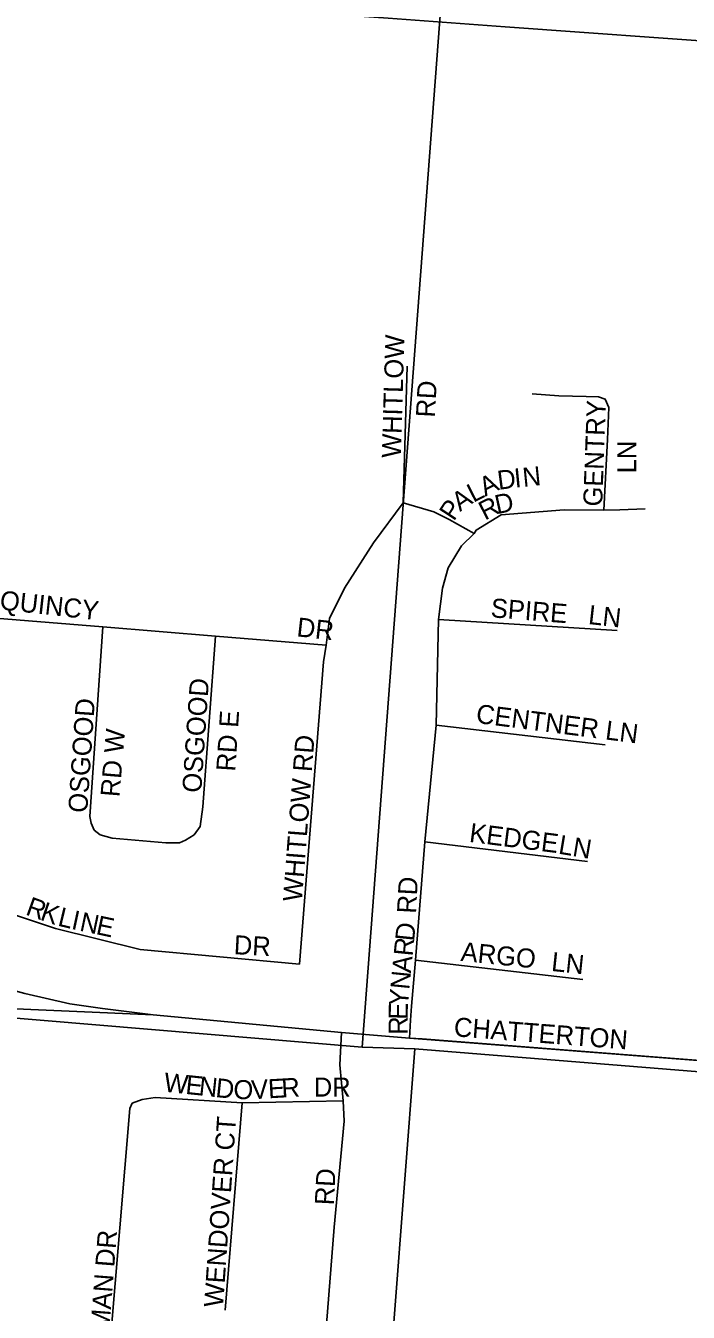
# Model space of a CAD drawing. Extents: x 0 to 34, y 0 to 22.
# Drawn here: x 8.094 to 8.423, y 17.781 to 18.421 of the extents above; entities that cross this region are included whole.
import ezdxf

# ---------------------------------------------------------------- set-up
doc = ezdxf.new("R2010")
doc.units = 0
for name, color, linetype in [('GM_X_City_Street', 7, 'Continuous'), ('GM_X_City_Street_Text', 7, 'Continuous'), ('GM_X_County_Road', 7, 'Continuous'), ('GM_X_Section', 7, 'Continuous'), ('GM_X_Township', 7, 'Continuous'), ('GM_X_Township_Subdivision', 7, 'Continuous'), ('GM_X_Township_Subdivision_Text', 7, 'Continuous')]:
    doc.layers.add(name, color=color, linetype=linetype)

msp = doc.modelspace()

# ---------------------------------------------------------------- linework, layer by layer
at = {"layer": 'GM_X_City_Street'}
for points in [[(7.61286, 18.47677), (7.73377, 18.46739), (7.82057, 18.46016), (7.91346, 18.4521), (8.05978, 18.44059), (8.20725, 18.42941), (8.274, 18.42481), (8.3322, 18.42053), (8.44761, 18.41231)], [(8.28157, 18.18394), (8.28355, 18.25186)], [(8.38117, 18.18027), (8.383, 18.2153), (8.3837, 18.23122), (8.38189, 18.23543), (8.37851, 18.23664), (8.37247, 18.23676), (8.35886, 18.23704), (8.34565, 18.23806)], [(8.28157, 18.18394), (8.29684, 18.17948), (8.30432, 18.17553), (8.31679, 18.16867)], [(8.31679, 18.16867), (8.31783, 18.17032), (8.33016, 18.17796), (8.36147, 18.18046), (8.38117, 18.18027), (8.38918, 18.18046), (8.4017, 18.18094)], [(8.28461, 17.91779), (8.2851, 17.92667), (8.2856, 17.9336), (8.28772, 17.95646), (8.29237, 18.01529), (8.29788, 18.07327), (8.29913, 18.12584), (8.30099, 18.14145), (8.30383, 18.15163), (8.31049, 18.16244), (8.31679, 18.16867)], [(8.29913, 18.12584), (8.38789, 18.12032)], [(8.29788, 18.07327), (8.38184, 18.06352)], [(8.29237, 18.01529), (8.37311, 18.00563)], [(8.28772, 17.95646), (8.3708, 17.94686)], [(8.2909, 17.9173), (8.63956, 17.89017), (9.29091, 17.83807)]]:
    msp.add_lwpolyline(points, dxfattribs=at)
at = {"layer": 'GM_X_County_Road'}
for points in [[(7.6551, 18.02038), (7.67615, 18.02597), (7.69834, 18.03139), (7.71725, 18.03583), (7.72744, 18.03764), (7.73747, 18.03847), (7.75375, 18.0383), (7.77627, 18.03682), (7.81129, 18.03271), (7.84861, 18.0258), (7.86752, 18.02153), (7.88712, 18.01651), (7.92611, 18.0042), (7.95605, 17.99275), (7.98227, 17.98158), (8.00743, 17.96991), (8.01844, 17.96498), (8.02732, 17.96136), (8.04475, 17.95429), (8.06973, 17.9464), (8.09357, 17.93998), (8.11592, 17.93484), (8.1322, 17.93242), (8.1521, 17.92995)], [(8.1521, 17.92995), (8.15736, 17.9293), (8.2509, 17.92059), (8.28461, 17.91779), (8.2909, 17.9173)]]:
    msp.add_lwpolyline(points, dxfattribs=at)
at = {"layer": 'GM_X_Section'}
for points in [[(7.83199, 18.97493), (8.33817, 18.93281), (8.26119, 17.91328), (7.7594, 17.95531)], [(8.33817, 18.93281), (8.85845, 18.89016), (8.78533, 17.87214), (8.28732, 17.91243), (8.26119, 17.91328)], [(7.25608, 17.99704), (7.7594, 17.95531), (8.26119, 17.91328), (8.28732, 17.91243), (8.21553, 16.97509), (7.19182, 17.04453)], [(8.28732, 17.91243), (8.78533, 17.87214), (9.29851, 17.83319), (9.21917, 16.9042), (8.21553, 16.97509)]]:
    msp.add_lwpolyline(points, close=True, dxfattribs=at)
at = {"layer": 'GM_X_Township'}
for points in [[(5.51769, 18.13119), (5.87625, 18.1039), (6.03605, 18.09206), (6.63383, 18.04603), (6.72474, 18.03863), (6.7448, 18.03814), (6.76124, 18.03764), (6.90082, 18.02498), (7.39535, 17.98733), (7.4612, 17.98313), (7.48383, 17.98347), (7.50256, 17.98423), (7.57966, 17.97294), (7.66873, 17.96768), (7.96341, 17.93943), (7.99401, 17.9365), (8.15736, 17.9293), (8.25091, 17.92059), (8.28461, 17.91779), (8.63956, 17.89017), (9.29091, 17.83808), (9.37362, 17.83148), (9.4, 17.82945)], [(9.4, 17.82945), (9.37362, 17.83148), (9.29091, 17.83808), (8.63956, 17.89017), (8.28461, 17.91779), (8.25091, 17.92059), (8.15736, 17.9293), (7.99401, 17.9365), (7.96341, 17.93943), (7.66873, 17.96768), (7.57966, 17.97294), (7.50256, 17.98423), (7.48383, 17.98347), (7.4612, 17.98313), (7.39535, 17.98733), (6.90082, 18.02498), (6.76124, 18.03764), (6.7448, 18.03814), (6.72474, 18.03863), (6.63383, 18.04603), (6.03605, 18.09206), (5.87625, 18.1039), (5.51769, 18.13119)]]:
    msp.add_lwpolyline(points, dxfattribs=at)
at = {"layer": 'GM_X_Township_Subdivision'}
for points in [[(8.23009, 17.95456), (8.24199, 18.10479), (8.2432, 18.11304), (8.24499, 18.1264), (8.25244, 18.14148), (8.26684, 18.16404), (8.28157, 18.18394)], [(8.07888, 18.12659), (8.13236, 18.12218), (8.18831, 18.11757), (8.2432, 18.11304)], [(8.12802, 18.02112), (8.12656, 18.02457), (8.12585, 18.028), (8.13236, 18.12218)], [(8.17766, 18.01882), (8.18076, 18.02295), (8.18206, 18.03281), (8.18831, 18.11757)], [(7.91845, 18.0533), (7.92969, 18.04438), (7.94171, 18.03735), (7.9589, 18.02921), (7.97408, 18.02203), (8.00216, 18.01282), (8.01153, 18.00854), (8.05954, 17.98931), (8.06875, 17.98553), (8.10886, 17.97221), (8.15095, 17.96188), (8.23009, 17.95456)], [(8.12802, 18.02112), (8.13101, 18.01879), (8.13706, 18.01718), (8.16356, 18.01486), (8.17039, 18.01475), (8.17344, 18.01623), (8.17766, 18.01882)], [(8.22144, 17.49905), (8.23877, 17.71644), (8.24732, 17.8237), (8.25217, 17.87646), (8.25174, 17.88662), (8.25005, 17.90439), (8.2509, 17.92059)], [(8.13644, 17.72798), (8.13423, 17.73181), (8.13355, 17.73638), (8.14576, 17.88279), (8.14694, 17.88543)], [(8.14694, 17.88543), (8.1519, 17.88725), (8.15836, 17.88829), (8.20157, 17.88552), (8.25174, 17.88662)], [(8.19304, 17.78253), (8.20157, 17.88552)]]:
    msp.add_lwpolyline(points, dxfattribs=at)

# ---------------------------------------------------------------- texts
at = {"layer": 'GM_X_City_Street_Text'}
for s, rotation, p in [('WHITLOW', 88.31625, (8.28037, 18.20612)), ('RD', 86.98901, (8.29729, 18.22615)), ('GENTRY', 87.9557, (8.38037, 18.18196)), ('LN', 90, (8.39731, 18.19857)), ('D', 7.47476, (8.32893, 18.19032)), ('I', 5.69319, (8.33711, 18.19139)), ('N', 5.68677, (8.34125, 18.19181)), ('L', 26.78499, (8.31634, 18.18381)), ('A', 26.75076, (8.32229, 18.18681)), ('A', 34.29016, (8.30973, 18.17928)), ('R', 27.37963, (8.32217, 18.17495)), ('D', 12.29171, (8.32821, 18.17818)), ('P', 56.57518, (8.30674, 18.17441)), ('SPIRE', 355.48827, (8.32479, 18.12701)), ('LN', 353.65181, (8.37317, 18.12367)), ('CENTNER LN', 352.71239, (8.31737, 18.0745)), ('KEDGE', 352.72451, (8.31404, 18.01533)), ('LN', 350.5298, (8.35827, 18.00949)), ('RD', 86.98901, (8.2879, 17.97949)), ('D', 84.28505, (8.28693, 17.96567)), ('R', 84.28457, (8.28619, 17.95821)), ('ARGO', 354.14185, (8.30983, 17.95617)), ('A', 84.28505, (8.28536, 17.94991)), ('LN', 353.99459, (8.35483, 17.95117)), ('N', 84.28505, (8.28453, 17.94162)), ('Y', 85.36159, (8.28386, 17.93336)), ('E', 88.98915, (8.28375, 17.92686)), ('R', 89.87855, (8.28373, 17.9194)), ('CHATTERTON', 355.6489, (8.30645, 17.91868))]:
    msp.add_text(s, height=0.00947, rotation=rotation, dxfattribs=at).set_placement(p)
at = {"layer": 'GM_X_Township_Subdivision_Text'}
for s, height, rotation, p in [('QUINCY', 0.00947, 353.65936, (8.08083, 18.13091)), ('DR', 0.00947, 353.66381, (8.22833, 18.11754)), ('OSGOOD', 0.00947, 86.05713, (8.1812, 18.03952)), ('OSGOOD', 0.00947, 86.05688, (8.12454, 18.02953)), ('RD E', 0.00947, 86.31087, (8.19812, 18.05014)), ('RD W', 0.00947, 85.23886, (8.1406, 18.03738)), ('WHITLOW RD', 0.00947, 85.60129, (8.2312, 17.98537)), ('R', 0.00947, 340.2057, (8.09352, 17.9793)), ('K', 0.00947, 341.07287, (8.10073, 17.97671)), ('L', 0.00947, 346.4294, (8.10954, 17.97373)), ('I', 0.00947, 347.90415, (8.11628, 17.97211)), ('N', 0.00947, 348.02834, (8.12038, 17.97123)), ('E', 0.00947, 348.02881, (8.12853, 17.9695)), ('DR', 0.00947, 356.98902, (8.19724, 17.95948)), ('W', 0.00947, 353.98659, (8.16234, 17.89117)), ('E', 0.00947, 354.00622, (8.17312, 17.89003)), ('N', 0.00947, 353.97841, (8.17974, 17.88934)), ('D', 0.00947, 354.0112, (8.18804, 17.88846)), ('E', 0.00947, 3.27975, (8.21465, 17.88778)), ('R', 0.00947, 3.25663, (8.2213, 17.88816)), ('DR', 0.00947, 0.00001, (8.23715, 17.88868)), ('O', 0.00947, 358.31514, (8.1971, 17.88754)), ('V', 0.00947, 3.26268, (8.20632, 17.88731)), ('WENDOVER CT', 0.0094697, 86.03542, (8.19203, 17.78369)), ('RD', 0.00947, 86.98901, (8.24704, 17.8345)), ('PORTMAN DR', 0.00947, 85.60129, (8.13287, 17.73704))]:
    msp.add_text(s, height=height, rotation=rotation, dxfattribs=at).set_placement(p)

doc.saveas('drawing.dxf')
